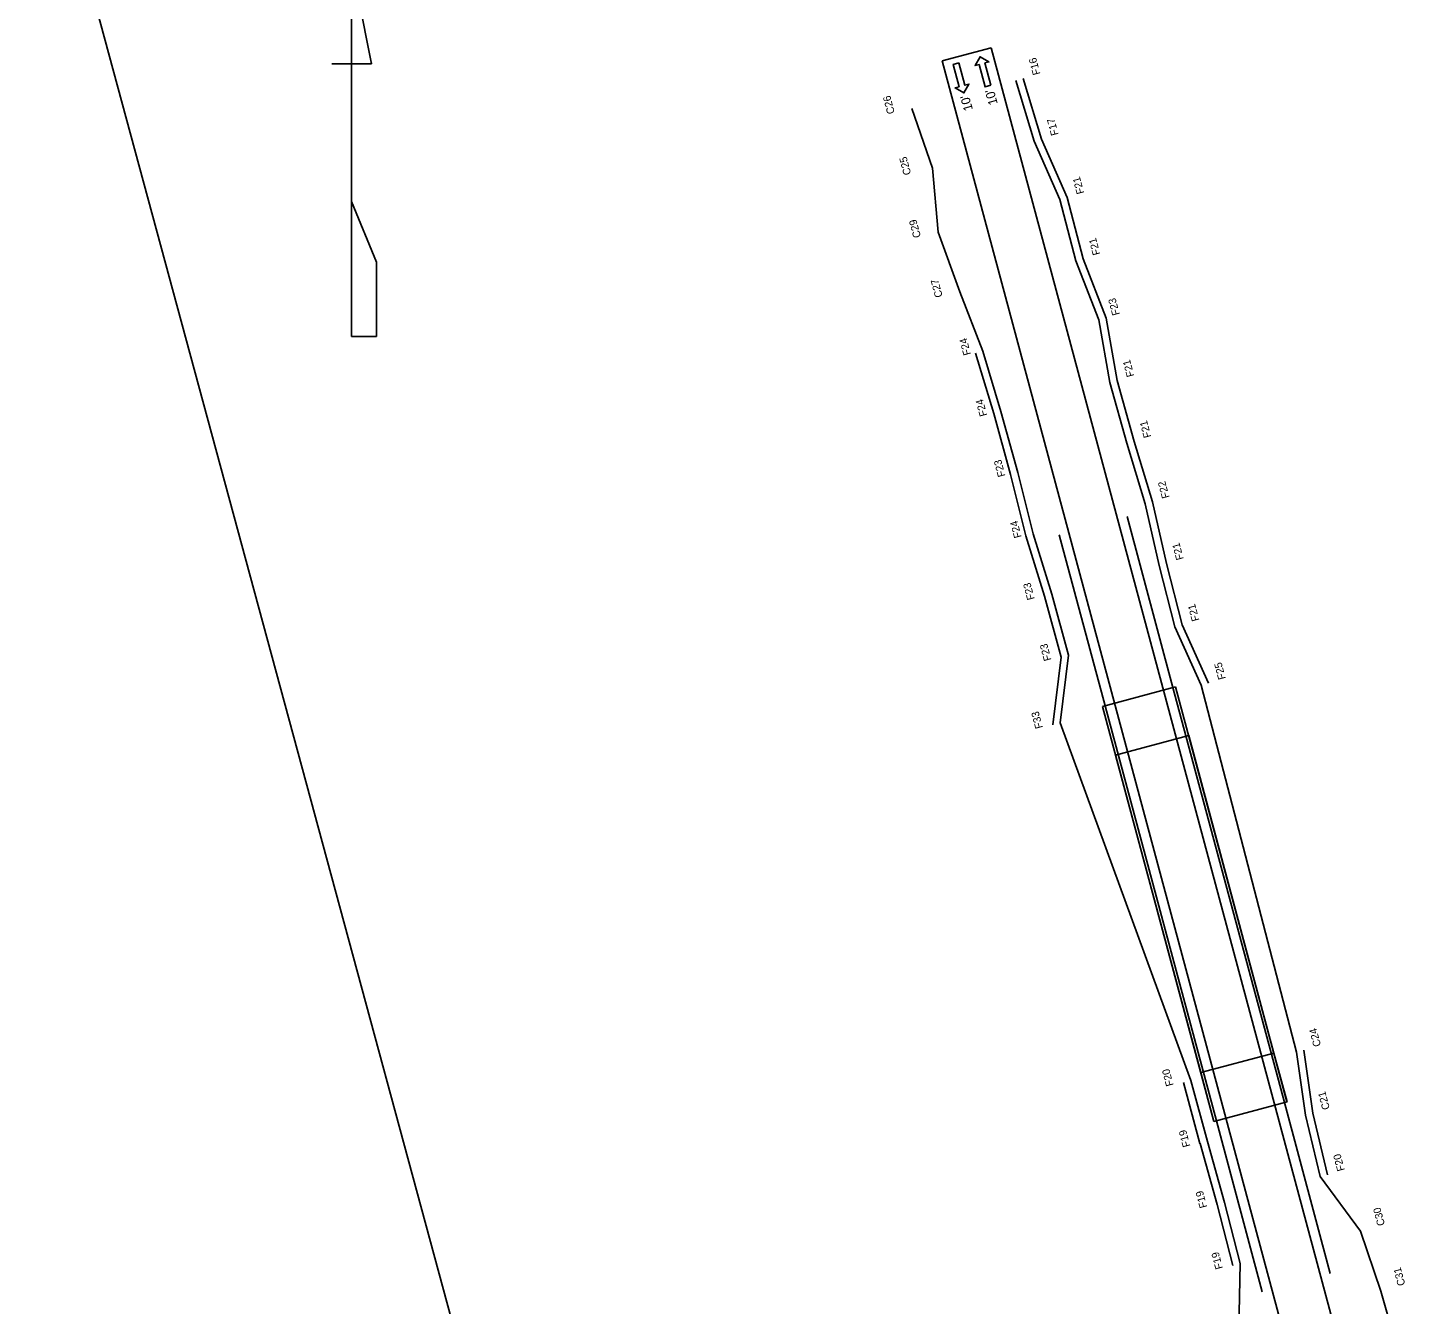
# Model space of a CAD drawing. Extents: x 1791526 to 1792446, y 1143210 to 1144425.
# Drawn here: x 1791526 to 1792080, y 1143640 to 1144145 of the extents above; entities that cross this region are included whole.
import ezdxf

# ---------------------------------------------------------------- set-up
doc = ezdxf.new("R2010")
doc.units = 0
for name, color, linetype in [('RD_EX_Misc', 7, 'Continuous'), ('RD_PD_Bridge', 7, 'Continuous'), ('RD_PD_CstnLmt', 7, 'Continuous'), ('RD_PD_CstnLmt_TX', 7, 'Continuous'), ('RD_PD_DR_ErosCtrl', 7, 'Continuous'), ('RD_PD_Final_TrvlWay', 7, 'Continuous'), ('RD_PD_Final_TX', 7, 'Continuous'), ('RD_PD_GR', 7, 'Continuous'), ('RD_SHT_TX', 7, 'Continuous'), ('RD_Sketch2', 7, 'Continuous')]:
    doc.layers.add(name, color=color, linetype=linetype)

msp = doc.modelspace()

# ---------------------------------------------------------------- linework, layer by layer
at = {"layer": 'RD_EX_Misc'}
for p, q in [((1791662.22, 1144130.92), (1791654.38, 1144170.13)), ((1791654.38, 1144170.13), (1791654.38, 1144130.92)), ((1791646.54, 1144130.92), (1791654.38, 1144130.92)), ((1791654.38, 1144076.53), (1791654.38, 1144130.92)), ((1791654.38, 1144130.92), (1791662.22, 1144130.92)), ((1791662.22, 1144130.92), (1791662.22, 1144131.39)), ((1791664.18, 1144052.52), (1791654.38, 1144076.53)), ((1791654.38, 1144076.53), (1791654.38, 1144023.12)), ((1791664.18, 1144023.12), (1791664.18, 1144052.79)), ((1791664.18, 1144052.79), (1791664.18, 1144052.52)), ((1791654.38, 1144023.12), (1791664.18, 1144023.12))]:
    msp.add_line(p, q, dxfattribs=at)
at = {"layer": 'RD_PD_Bridge'}
for p, q in [((1791951.35, 1143876.81), (1791980.32, 1143884.59)), ((1792023.34, 1143720.12), (1791979.27, 1143884.31)), ((1792024.3, 1143720.37), (1791980.24, 1143884.57)), ((1791995.49, 1143712.64), (1791951.43, 1143876.83)), ((1791996.45, 1143712.9), (1791952.39, 1143877.09)), ((1792019.2, 1143739.71), (1792024.38, 1143720.4)), ((1791990.22, 1143731.94), (1791995.41, 1143712.62)), ((1792024.38, 1143720.4), (1791995.41, 1143712.62))]:
    msp.add_line(p, q, dxfattribs=at)
msp.add_lwpolyline([(1791990.22, 1143731.94), (1791956.53, 1143857.5), (1791985.5, 1143865.27), (1792019.2, 1143739.71)], close=True, dxfattribs=at)
at = {"layer": 'RD_PD_CstnLmt'}
for p, q in [((1791924.34, 1144100.45), (1791917.13, 1144124.4)), ((1791884.08, 1144089.65), (1791876.03, 1144113.37)), ((1791934.48, 1144077.29), (1791924.34, 1144100.45)), ((1791886.37, 1144064.38), (1791884.08, 1144089.65)), ((1791940.85, 1144053.12), (1791934.48, 1144077.29)), ((1791894.95, 1144040.8), (1791886.37, 1144064.38)), ((1791949.9, 1144029.66), (1791940.85, 1144053.12)), ((1791904.07, 1144017.36), (1791894.95, 1144040.8)), ((1791954.3, 1144004.96), (1791949.9, 1144029.66)), ((1791911.23, 1143993.4), (1791904.07, 1144017.36)), ((1791961, 1143980.87), (1791954.3, 1144004.96)), ((1791917.91, 1143969.31), (1791911.23, 1143993.4)), ((1791968.22, 1143956.92), (1791961, 1143980.87)), ((1791923.97, 1143945.05), (1791917.91, 1143969.31)), ((1791973.84, 1143932.55), (1791968.22, 1143956.92)), ((1791931.37, 1143921.15), (1791923.97, 1143945.05)), ((1791980.03, 1143908.32), (1791973.84, 1143932.55)), ((1791937.98, 1143897.04), (1791931.37, 1143921.15)), ((1791990.47, 1143885.24), (1791980.03, 1143908.32)), ((1791934.6, 1143870.25), (1791937.98, 1143897.04)), ((1792028.15, 1143740.05), (1791990.47, 1143885.24)), ((1791986.3, 1143728.81), (1791934.6, 1143870.25)), ((1792031.64, 1143715.1), (1792028.15, 1143740.05)), ((1791992.93, 1143704.71), (1791986.3, 1143728.81)), ((1792037.54, 1143690.8), (1792031.64, 1143715.1)), ((1791999.58, 1143680.61), (1791992.93, 1143704.71)), ((1792053.44, 1143669.18), (1792037.54, 1143690.8)), ((1792005.83, 1143656.4), (1791999.58, 1143680.61)), ((1792061.49, 1143645.45), (1792053.44, 1143669.18)), ((1792005.27, 1143630.37), (1792005.83, 1143656.4)), ((1792068.35, 1143621.41), (1792061.49, 1143645.45))]:
    msp.add_line(p, q, dxfattribs=at)
at = {"layer": 'RD_PD_DR_ErosCtrl'}
for points in [[(1791937.37, 1144078.07), (1791927.24, 1144101.23), (1791920.03, 1144125.18)], [(1791993.37, 1143886.02), (1791982.93, 1143909.1), (1791976.74, 1143933.32), (1791971.12, 1143957.7), (1791963.9, 1143981.65), (1791957.2, 1144005.73), (1791952.79, 1144030.44), (1791943.75, 1144053.89), (1791937.37, 1144078.07)], [(1791931.7, 1143869.47), (1791935.08, 1143896.26), (1791928.48, 1143920.37), (1791921.08, 1143944.27), (1791915.01, 1143968.53), (1791908.34, 1143992.62), (1791901.17, 1144016.58)], [(1792040.44, 1143691.57), (1792034.54, 1143715.87), (1792031.05, 1143740.82)], [(1792002.94, 1143655.63), (1791996.69, 1143679.83), (1791990.03, 1143703.93), (1791989.88, 1143703.89), (1791983.4, 1143728.04)]]:
    msp.add_lwpolyline(points, dxfattribs=at)
at = {"layer": 'RD_PD_Final_TrvlWay'}
for p, q in [((1791888.01, 1144132.12), (1791907.33, 1144137.3)), ((1792066.72, 1143543.32), (1791907.33, 1144137.3)), ((1792047.41, 1143538.14), (1791888.01, 1144132.12))]:
    msp.add_line(p, q, dxfattribs=at)
at = {"layer": 'RD_PD_Final_TX'}
for points in [[(1791907.27, 1144122.49), (1791904.96, 1144121.86), (1791902.56, 1144130.71), (1791900.99, 1144130.29), (1791902.98, 1144133.76), (1791906.45, 1144131.77), (1791904.87, 1144131.34)], [(1791894.59, 1144131.38), (1791892.27, 1144130.75), (1791894.67, 1144121.9), (1791893.1, 1144121.47), (1791896.57, 1144119.48), (1791898.56, 1144122.95), (1791896.98, 1144122.52)]]:
    msp.add_lwpolyline(points, close=True, dxfattribs=at)
at = {"layer": 'RD_PD_GR'}
for p, q in [((1791961.13, 1143951.91), (1791979.27, 1143884.31)), ((1791952.39, 1143877.09), (1791934.25, 1143944.7)), ((1792023.34, 1143720.12), (1792041.48, 1143652.51)), ((1792014.6, 1143645.29), (1791996.45, 1143712.9))]:
    msp.add_line(p, q, dxfattribs=at)
at = {"layer": 'RD_Sketch2'}
msp.add_lwpolyline([(1792445.77, 1143382.88), (1792163.4, 1144425.31), (1791526.36, 1144252.75), (1791808.72, 1143210.32)], close=True, dxfattribs=at)

# ---------------------------------------------------------------- texts
at = {"layer": 'RD_PD_CstnLmt_TX'}
for s, p in [('F16', (1791926.85, 1144127)), ('C26', (1791869.27, 1144111.56)), ('F17', (1791934.05, 1144103.05)), ('C25', (1791875.74, 1144087.41)), ('F21', (1791944.19, 1144079.89)), ('C29', (1791879.6, 1144062.57)), ('F21', (1791950.56, 1144055.72)), ('C27', (1791888.19, 1144038.98)), ('F23', (1791958.27, 1144031.9)), ('F24', (1791899.39, 1144016.11)), ('F21', (1791964.01, 1144007.56)), ('F24', (1791905.82, 1143991.95)), ('F21', (1791970.72, 1143983.47)), ('F23', (1791913.03, 1143968)), ('F22', (1791977.93, 1143959.52)), ('F24', (1791919.45, 1143943.84)), ('F21', (1791983.55, 1143935.15)), ('F23', (1791924.61, 1143919.34)), ('F21', (1791989.74, 1143910.92)), ('F23', (1791931.22, 1143895.22)), ('F25', (1792000.19, 1143887.84)), ('F33', (1791927.84, 1143868.43)), ('C24', (1792037.87, 1143742.65)), ('F20', (1791979.54, 1143727)), ('C21', (1792041.36, 1143717.7)), ('F19', (1791986.17, 1143702.89)), ('F20', (1792047.26, 1143693.4)), ('F19', (1791992.82, 1143678.8)), ('C30', (1792063.16, 1143671.78)), ('F19', (1791999.07, 1143654.59)), ('C31', (1792071.2, 1143648.05))]:
    msp.add_text(s, height=3, rotation=105.0215, dxfattribs=at).set_placement(p)
at = {"layer": 'RD_SHT_TX'}
for p in [(1791900.18, 1144112.92), (1791910, 1144115.24)]:
    msp.add_text("10'", height=3.6, rotation=106.0269, dxfattribs=at).set_placement(p)

doc.saveas('drawing.dxf')
